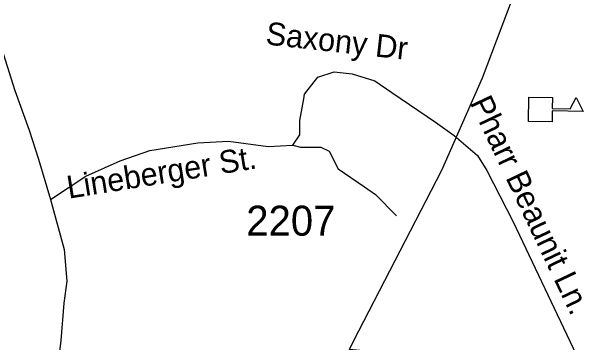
# Model space of a CAD drawing. Extents: x 1364363 to 1407445, y 538563 to 573342.
# Drawn here: x 1373779 to 1376165, y 561783 to 563162 of the extents above; entities that cross this region are included whole.
import ezdxf

# ---------------------------------------------------------------- set-up
doc = ezdxf.new("R2010")
doc.units = 0
for name, color, linetype in [('Exist Boundary Political City Limit New', 7, 'Continuous'), ('Exist Cultural Educational Facility High CELL', 7, 'Continuous'), ('Exist Road Secondary Type 51 Attributed', 7, 'Continuous'), ('Exist Road Secondary Type 51 Label', 7, 'Continuous'), ('Exist Road Secondary Type 51 Number Label', 7, 'Continuous')]:
    doc.layers.add(name, color=color, linetype=linetype)

msp = doc.modelspace()

# ---------------------------------------------------------------- linework, layer by layer
at = {"layer": 'Exist Boundary Political City Limit New'}
for points in [[(1375206.1, 561788.9), (1375573.2, 562500.8), (1375743.9, 562885.2), (1375884.1, 563257.4), (1375926.8, 563806.6), (1376146.1, 564599.8), (1376237.6, 564700.5), (1376466.9, 564836.6)], [(1376374.4, 560270.1), (1376256.2, 560605.1), (1376095, 561149.6), (1375994.4, 561314.9), (1375861.4, 561440), (1375696.1, 561585.2), (1375506.8, 561673.9), (1375261, 561746.6), (1375188.5, 561754.6), (1375206.1, 561788.9)]]:
    msp.add_lwpolyline(points, dxfattribs=at)
at = {"layer": 'Exist Cultural Educational Facility High CELL'}
msp.add_lwpolyline([(1375937.2, 562805.3), (1376035.1, 562803.6), (1376034.3, 562757.5), (1376109.4, 562756.2), (1376134.5, 562802.8), (1376162.6, 562745.6), (1376034.1, 562747.9), (1376033.3, 562701.9), (1375935.4, 562703.7)], close=True, dxfattribs=at)
at = {"layer": 'Exist Road Secondary Type 51 Attributed'}
for points in [[(1373744.7, 562987), (1373793.6, 562832), (1373853.1, 562666.8), (1373892, 562546.7), (1373942.7, 562378.3)], [(1374953.1, 562605.1), (1374982.3, 562647.3), (1374982.3, 562707.3), (1374998.6, 562798.2), (1375001.8, 562817.7), (1375057, 562887.6), (1375125.1, 562910.4), (1375199.8, 562902.1), (1375293.9, 562872.9), (1375365.2, 562824.2), (1375547, 562700.8), (1375624.8, 562645.6), (1375722.2, 562561.2), (1375761.1, 562499.5), (1375871.5, 562285.3), (1376134.3, 561733.3)], [(1373942.7, 562378.3), (1374090, 562475.3), (1374232.7, 562540.2), (1374356.1, 562582.4), (1374557.2, 562614.9), (1374683.8, 562621.4), (1374849.3, 562598.6), (1374953.1, 562605.1)], [(1374953.1, 562605.1), (1374984.3, 562596.7), (1375070, 562596.7), (1375103.7, 562579.8), (1375141.3, 562506), (1375251.7, 562431.4), (1375297.1, 562398.9), (1375384.7, 562311.2)], [(1373942.7, 562378.3), (1373999.1, 562170), (1374009.9, 562038.4), (1373997.8, 561947.1), (1373985.6, 561791.8), (1373964.3, 561624.3), (1373967.3, 561526.9), (1373979.5, 561435.5), (1374029, 561311.7)]]:
    msp.add_lwpolyline(points, dxfattribs=at)

# ---------------------------------------------------------------- texts
at = {"layer": 'Exist Road Secondary Type 51 Label'}
for s, rotation, p in [('Saxony Dr', 353.7188, (1374836.7, 563024.6)), ('Pharr Beaunit Ln.', 295.4647, (1375689.4, 562782)), ('Lineberger St.', 9.168, (1374018.4, 562381.8))]:
    msp.add_text(s, height=95, rotation=rotation, dxfattribs=at).set_placement(p)
at = {"layer": 'Exist Road Secondary Type 51 Number Label'}
msp.add_text('2207', height=125, dxfattribs=at).set_placement((1374758.4, 562227.8))

doc.saveas('drawing.dxf')
